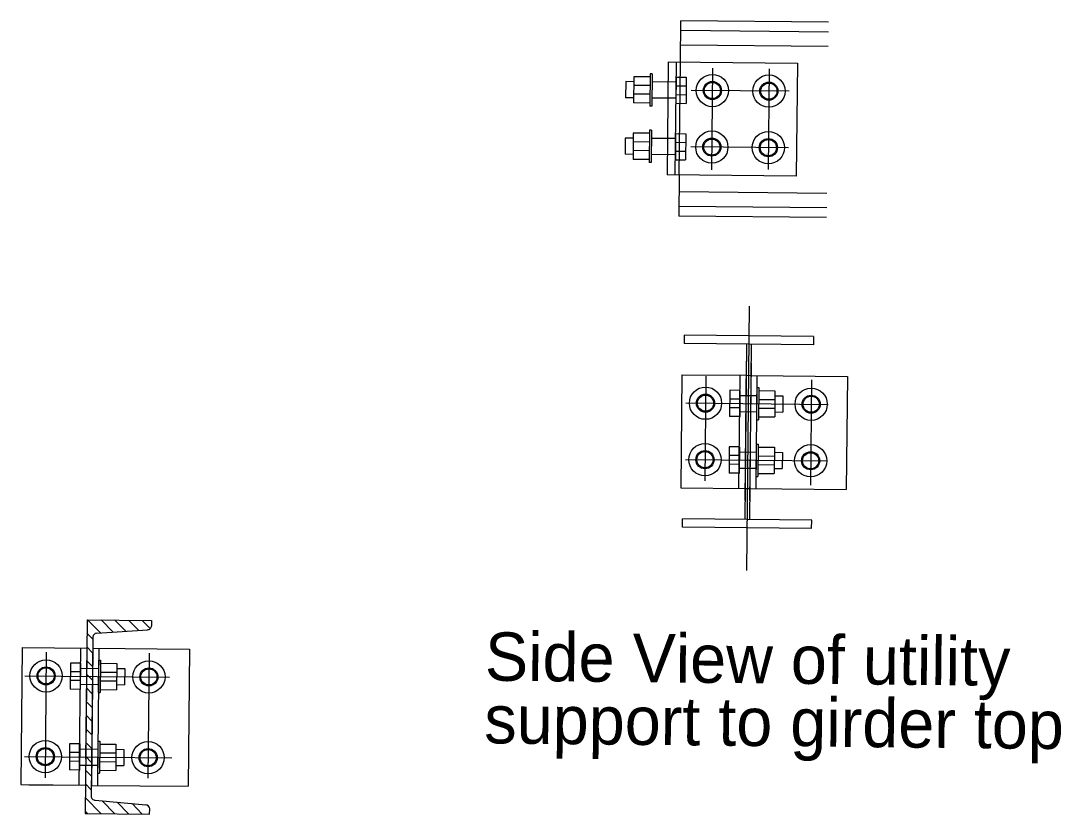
# Model space of a CAD drawing. Extents: x 632312 to 632885, y 378199 to 378534.
# Drawn here: x 632384.32 to 632389.7, y 378392.46 to 378396.56 of the extents above; entities that cross this region are included whole.
import ezdxf

# ---------------------------------------------------------------- set-up
doc = ezdxf.new("R2010")
doc.units = 0
for name, color, linetype in [('B_Boring', 7, 'Continuous'), ('R_Proposed Const Limits Cut', 7, 'Continuous'), ('R_Wall', 7, 'Continuous'), ('SHT_Dimensions', 7, 'Continuous'), ('USACE_Easement', 7, 'Continuous')]:
    doc.layers.add(name, color=color, linetype=linetype)

msp = doc.modelspace()

# ---------------------------------------------------------------- linework, layer by layer
at = {"layer": 'B_Boring'}
for p, q in [((632387.7302, 378396.3471), (632387.7323, 378396.5596)), ((632388.4951, 378396.552), (632387.7323, 378396.5596)), ((632388.4946, 378396.5016), (632387.7318, 378396.5091)), ((632387.6677, 378396.3477), (632387.6619, 378395.7644)), ((632387.6677, 378396.3477), (632388.3344, 378396.3411)), ((632387.7036, 378395.764), (632387.7094, 378396.3473)), ((632388.3344, 378396.3411), (632388.3286, 378395.7578)), ((632387.4899, 378396.2713), (632387.4885, 378396.1359)), ((632387.5732, 378396.2705), (632387.4899, 378396.2713)), ((632387.5734, 378396.2861), (632387.5717, 378396.1195)), ((632387.5838, 378396.286), (632387.5734, 378396.2861)), ((632387.5838, 378396.286), (632387.5821, 378396.1194)), ((632387.7086, 378396.2692), (632387.7073, 378396.1338)), ((632387.7086, 378396.2692), (632387.7607, 378396.2686)), ((632387.7607, 378396.2686), (632387.7593, 378396.1332)), ((632387.4479, 378396.2457), (632387.4471, 378396.1624)), ((632387.4896, 378396.2453), (632387.4479, 378396.2457)), ((632387.5728, 378396.2254), (632387.4894, 378396.2262)), ((632387.7084, 378396.2431), (632387.5834, 378396.2444)), ((632387.7082, 378396.224), (632387.7602, 378396.2235)), ((632387.4888, 378396.162), (632387.4471, 378396.1624)), ((632387.5723, 378396.1802), (632387.489, 378396.1811)), ((632387.7075, 378396.1598), (632387.5825, 378396.161)), ((632387.7077, 378396.1789), (632387.7598, 378396.1784)), ((632387.5719, 378396.1351), (632387.4885, 378396.1359)), ((632387.5821, 378396.1194), (632387.5717, 378396.1195)), ((632387.7073, 378396.1338), (632387.7593, 378396.1332)), ((632387.5705, 378395.9945), (632387.5688, 378395.8278)), ((632387.5809, 378395.9944), (632387.5705, 378395.9945)), ((632387.5809, 378395.9944), (632387.5792, 378395.8277)), ((632387.445, 378395.9541), (632387.4442, 378395.8707)), ((632387.4867, 378395.9536), (632387.445, 378395.9541)), ((632387.487, 378395.9797), (632387.4856, 378395.8443)), ((632387.5699, 378395.9337), (632387.4865, 378395.9346)), ((632387.5703, 378395.9789), (632387.487, 378395.9797)), ((632387.7055, 378395.9515), (632387.5805, 378395.9527)), ((632387.7057, 378395.9775), (632387.7044, 378395.8421)), ((632387.7053, 378395.9324), (632387.7573, 378395.9319)), ((632387.7057, 378395.9775), (632387.7578, 378395.977)), ((632387.7578, 378395.977), (632387.7564, 378395.8416)), ((632387.5694, 378395.8886), (632387.4861, 378395.8894)), ((632387.7048, 378395.8872), (632387.7569, 378395.8867)), ((632387.4859, 378395.8703), (632387.4442, 378395.8707)), ((632387.569, 378395.8435), (632387.4856, 378395.8443)), ((632387.5792, 378395.8277), (632387.5688, 378395.8278)), ((632387.7046, 378395.8681), (632387.5796, 378395.8694)), ((632387.7044, 378395.8421), (632387.7564, 378395.8416)), ((632388.3286, 378395.7578), (632387.6619, 378395.7644)), ((632387.7244, 378395.7638), (632387.7223, 378395.5513)), ((632388.4851, 378395.5437), (632387.7223, 378395.5513)), ((632388.4856, 378395.5941), (632387.7228, 378395.6017)), ((632387.7503, 378394.9372), (632387.7498, 378394.8943)), ((632388.4177, 378394.9306), (632387.7503, 378394.9372)), ((632388.4177, 378394.9306), (632388.4173, 378394.8877)), ((632388.4173, 378394.8877), (632387.7498, 378394.8943)), ((632388.0713, 378394.8911), (632388.0623, 378393.9853)), ((632388.0959, 378394.8909), (632388.0869, 378393.9851)), ((632387.7382, 378394.7332), (632387.7324, 378394.1499)), ((632387.7382, 378394.7332), (632388.0697, 378394.7299)), ((632388.0326, 378394.1469), (632388.0384, 378394.7302)), ((632388.0943, 378394.7297), (632388.5923, 378394.7247)), ((632388.1255, 378394.7293), (632388.1197, 378394.146)), ((632388.5923, 378394.7247), (632388.5865, 378394.1414)), ((632387.9855, 378394.6526), (632387.9842, 378394.5172)), ((632388.0376, 378394.6521), (632387.9855, 378394.6526)), ((632388.0376, 378394.6521), (632388.0363, 378394.5167)), ((632388.1249, 378394.6668), (632388.1232, 378394.5002)), ((632388.1249, 378394.6668), (632388.1353, 378394.6667)), ((632388.1353, 378394.6667), (632388.1336, 378394.5001)), ((632388.1351, 378394.6511), (632388.2185, 378394.6503)), ((632388.2185, 378394.6503), (632388.2171, 378394.5149)), ((632388.0372, 378394.607), (632387.9851, 378394.6075)), ((632388.1347, 378394.606), (632388.218, 378394.6052)), ((632388.2182, 378394.6242), (632388.2599, 378394.6238)), ((632388.2599, 378394.6238), (632388.259, 378394.5405)), ((632388.0367, 378394.5618), (632387.9847, 378394.5623)), ((632388.1342, 378394.5608), (632388.2176, 378394.56)), ((632388.2174, 378394.5409), (632388.259, 378394.5405)), ((632388.0363, 378394.5167), (632387.9842, 378394.5172)), ((632388.1232, 378394.5002), (632388.1336, 378394.5001)), ((632388.1338, 378394.5157), (632388.2171, 378394.5149)), ((632388.122, 378394.3752), (632388.1203, 378394.2085)), ((632388.122, 378394.3752), (632388.1324, 378394.3751)), ((632388.1324, 378394.3751), (632388.1307, 378394.2084)), ((632387.9826, 378394.3609), (632387.9813, 378394.2255)), ((632388.0343, 378394.3153), (632387.9822, 378394.3158)), ((632388.0347, 378394.3604), (632387.9826, 378394.3609)), ((632388.0347, 378394.3604), (632388.0334, 378394.225)), ((632388.1322, 378394.3594), (632388.2156, 378394.3586)), ((632388.2156, 378394.3586), (632388.2142, 378394.2232)), ((632388.2153, 378394.3326), (632388.257, 378394.3321)), ((632388.257, 378394.3321), (632388.2561, 378394.2488)), ((632388.0338, 378394.2701), (632387.9818, 378394.2706)), ((632388.1313, 378394.2692), (632388.2147, 378394.2683)), ((632388.1318, 378394.3143), (632388.2151, 378394.3135)), ((632388.0334, 378394.225), (632387.9813, 378394.2255)), ((632388.1203, 378394.2085), (632388.1307, 378394.2084)), ((632388.1309, 378394.224), (632388.2142, 378394.2232)), ((632388.2145, 378394.2492), (632388.2561, 378394.2488)), ((632387.7324, 378394.1499), (632388.0639, 378394.1466)), ((632388.0885, 378394.1463), (632388.5865, 378394.1414)), ((632387.7404, 378393.9456), (632387.7408, 378393.9885)), ((632388.4079, 378393.939), (632387.7404, 378393.9456)), ((632388.4083, 378393.9819), (632387.7408, 378393.9885)), ((632388.4079, 378393.939), (632388.4083, 378393.9819)), ((632384.6666, 378393.4682), (632384.6566, 378392.4683)), ((632384.6666, 378393.4682), (632384.9998, 378393.4649)), ((632384.7356, 378393.4002), (632384.669, 378393.4682)), ((632384.8012, 378393.4048), (632384.7397, 378393.4675)), ((632384.8667, 378393.4094), (632384.8104, 378393.4668)), ((632384.9322, 378393.414), (632384.8811, 378393.4661)), ((632384.9933, 378393.4231), (632384.9518, 378393.4654)), ((632384.9998, 378393.4649), (632384.9996, 378393.4378)), ((632384.7175, 378393.399), (632384.9786, 378393.4172)), ((632384.6964, 378393.3688), (632384.6659, 378393.4)), ((632384.6965, 378393.3783), (632384.6883, 378392.5575)), ((632384.3318, 378393.3257), (632384.3247, 378392.6174)), ((632384.3318, 378393.3257), (632384.6651, 378393.3224)), ((632384.6268, 378392.6144), (632384.6339, 378393.3227)), ((632384.6957, 378393.2981), (632384.6652, 378393.3293)), ((632384.6959, 378393.3221), (632385.1959, 378393.3171)), ((632384.7272, 378393.3218), (632384.7201, 378392.6135)), ((632385.1959, 378393.3171), (632385.1889, 378392.6088)), ((632384.581, 378393.2451), (632384.5796, 378393.1097)), ((632384.6331, 378393.2446), (632384.581, 378393.2451)), ((632384.6331, 378393.2446), (632384.6317, 378393.1092)), ((632384.695, 378393.2274), (632384.6645, 378393.2586)), ((632384.7266, 378393.2593), (632384.7249, 378393.0926)), ((632384.7266, 378393.2593), (632384.737, 378393.2592)), ((632384.737, 378393.2592), (632384.7353, 378393.0925)), ((632384.7368, 378393.2435), (632384.8202, 378393.2427)), ((632384.8202, 378393.2427), (632384.8188, 378393.1073)), ((632384.6326, 378393.1994), (632384.5805, 378393.2)), ((632384.6943, 378393.1567), (632384.6638, 378393.1878)), ((632384.7364, 378393.1984), (632384.8197, 378393.1976)), ((632384.8199, 378393.2167), (632384.8616, 378393.2163)), ((632384.8616, 378393.2163), (632384.8607, 378393.1329)), ((632384.6322, 378393.1543), (632384.5801, 378393.1548)), ((632384.7359, 378393.1533), (632384.8193, 378393.1524)), ((632384.8191, 378393.1334), (632384.8607, 378393.1329)), ((632384.6317, 378393.1092), (632384.5796, 378393.1097)), ((632384.6936, 378393.086), (632384.6631, 378393.1171)), ((632384.7249, 378393.0926), (632384.7353, 378393.0925)), ((632384.7355, 378393.1081), (632384.8188, 378393.1073)), ((632384.6929, 378393.0153), (632384.6624, 378393.0464)), ((632384.6922, 378392.9446), (632384.6617, 378392.9757)), ((632384.6915, 378392.8739), (632384.661, 378392.905)), ((632384.5769, 378392.8284), (632384.5755, 378392.693)), ((632384.6289, 378392.8279), (632384.5769, 378392.8284)), ((632384.6289, 378392.8279), (632384.6276, 378392.6925)), ((632384.6908, 378392.8032), (632384.6602, 378392.8343)), ((632384.7224, 378392.8426), (632384.7208, 378392.676)), ((632384.7224, 378392.8426), (632384.7328, 378392.8425)), ((632384.7328, 378392.8425), (632384.7312, 378392.6759)), ((632384.7327, 378392.8269), (632384.816, 378392.8261)), ((632384.816, 378392.8261), (632384.8147, 378392.6907)), ((632384.6285, 378392.7828), (632384.5764, 378392.7833)), ((632384.6901, 378392.7325), (632384.6595, 378392.7636)), ((632384.7322, 378392.7818), (632384.8156, 378392.7809)), ((632384.8157, 378392.8), (632384.8574, 378392.7996)), ((632384.8574, 378392.7996), (632384.8566, 378392.7163)), ((632384.628, 378392.7377), (632384.576, 378392.7382)), ((632384.7318, 378392.7366), (632384.8151, 378392.7358)), ((632384.8149, 378392.7167), (632384.8566, 378392.7163)), ((632384.6276, 378392.6925), (632384.5755, 378392.693)), ((632384.6894, 378392.6618), (632384.6588, 378392.6929)), ((632384.7208, 378392.676), (632384.7312, 378392.6759)), ((632384.7313, 378392.6915), (632384.8147, 378392.6907)), ((632384.3247, 378392.6174), (632384.6581, 378392.6141)), ((632384.6887, 378392.5911), (632384.6581, 378392.6222)), ((632384.6889, 378392.6138), (632385.1889, 378392.6088)), ((632384.7398, 378392.4674), (632384.6574, 378392.5515)), ((632384.7089, 378392.5365), (632384.9696, 378392.5131)), ((632384.8105, 378392.4667), (632384.7454, 378392.5332)), ((632384.8812, 378392.466), (632384.8221, 378392.5263)), ((632384.9519, 378392.4653), (632384.8989, 378392.5194)), ((632384.9891, 378392.4988), (632384.9763, 378392.5119)), ((632384.9899, 378392.465), (632384.9902, 378392.4921)), ((632384.6597, 378392.4682), (632384.6566, 378392.4714)), ((632384.6566, 378392.4683), (632384.9899, 378392.465)), ((632384.6566, 378392.4683), (632384.9899, 378392.465)), ((632384.6691, 378392.4681), (632384.6567, 378392.4808))]:
    msp.add_line(p, q, dxfattribs=at)
for centre in [(632387.8954, 378396.1996), (632388.1871, 378396.1967), (632387.8925, 378395.9079), (632388.1842, 378395.905), (632387.8599, 378394.5861), (632388.4053, 378394.5807), (632387.857, 378394.2945), (632388.4024, 378394.289), (632384.4553, 378393.1786), (632384.9861, 378393.1734), (632384.4512, 378392.762), (632384.982, 378392.7567)]:
    msp.add_circle(centre, 0.0469, dxfattribs=at)
for centre, start, end in [((632384.9788, 378393.438), 269.4304, 359.4388), ((632384.7173, 378393.3781), 89.4304, 179.4304), ((632384.7091, 378392.5573), 179.4304, 269.4304), ((632384.9694, 378392.4923), 359.4304, 89.4304)]:
    msp.add_arc(centre, 0.0208, start, end, dxfattribs=at)
at = {"layer": 'R_Proposed Const Limits Cut'}
for p, q in [((632388.4939, 378396.427), (632387.7311, 378396.4346)), ((632387.7244, 378395.7638), (632387.7302, 378396.3471)), ((632388.4863, 378395.6687), (632387.7236, 378395.6763)), ((632388.0697, 378394.7299), (632388.0943, 378394.7297)), ((632388.0374, 378394.626), (632388.1245, 378394.6252)), ((632388.0365, 378394.5427), (632388.1236, 378394.5419)), ((632388.0345, 378394.3344), (632388.1216, 378394.3335)), ((632388.0336, 378394.251), (632388.1207, 378394.2502)), ((632388.0639, 378394.1466), (632388.0885, 378394.1463)), ((632384.6328, 378393.2185), (632384.7261, 378393.2176)), ((632384.632, 378393.1352), (632384.7253, 378393.1343)), ((632384.6287, 378392.8019), (632384.722, 378392.801)), ((632384.6278, 378392.7186), (632384.7212, 378392.7176))]:
    msp.add_line(p, q, dxfattribs=at)
for centre, radius in [((632387.8954, 378396.1996), 0.0833), ((632388.1871, 378396.1967), 0.0833), ((632387.8954, 378396.1996), 0.0417), ((632388.1871, 378396.1967), 0.0417), ((632387.8925, 378395.9079), 0.0833), ((632388.1842, 378395.905), 0.0833), ((632387.8925, 378395.9079), 0.0417), ((632388.1842, 378395.905), 0.0417), ((632387.8599, 378394.5861), 0.0833), ((632388.4053, 378394.5807), 0.0833), ((632387.8599, 378394.5861), 0.0417), ((632388.4053, 378394.5807), 0.0417), ((632387.857, 378394.2945), 0.0833), ((632388.4024, 378394.289), 0.0833), ((632387.857, 378394.2945), 0.0417), ((632388.4024, 378394.289), 0.0417), ((632384.4553, 378393.1786), 0.0833), ((632384.9861, 378393.1734), 0.0833), ((632384.4553, 378393.1786), 0.0417), ((632384.9861, 378393.1734), 0.0417), ((632384.4512, 378392.762), 0.0833), ((632384.982, 378392.7567), 0.0833), ((632384.4512, 378392.762), 0.0417), ((632384.982, 378392.7567), 0.0417)]:
    msp.add_circle(centre, radius, dxfattribs=at)
at = {"layer": 'R_Wall'}
for p, q in [((632387.8966, 378396.3152), (632387.8914, 378395.7907)), ((632388.1882, 378396.3123), (632388.1831, 378395.7922)), ((632388.2912, 378396.1957), (632387.7865, 378396.2007)), ((632388.2883, 378395.904), (632387.7836, 378395.909)), ((632388.0855, 378395.0869), (632388.0719, 378393.7227)), ((632387.8613, 378394.7253), (632387.8559, 378394.1857)), ((632388.4065, 378394.707), (632388.4011, 378394.1622)), ((632387.759, 378394.5871), (632388.4929, 378394.5798)), ((632387.7561, 378394.2955), (632388.49, 378394.2882)), ((632384.4565, 378393.3014), (632384.4501, 378392.6533)), ((632384.9874, 378393.2961), (632384.9809, 378392.651)), ((632384.3462, 378393.1797), (632385.0931, 378393.1723)), ((632384.3446, 378392.763), (632385.105, 378392.7555))]:
    msp.add_line(p, q, dxfattribs=at)
at = {"layer": 'SHT_Dimensions'}
for p, q in [((632388.0704, 378394.8028), (632388.0632, 378394.0841)), ((632388.0949, 378394.7921), (632388.0878, 378394.0838)), ((632384.6652, 378393.3328), (632384.6594, 378392.7495)), ((632384.6959, 378393.3221), (632384.6889, 378392.6138)), ((632384.3664, 378392.617), (632384.6581, 378392.6141))]:
    msp.add_line(p, q, dxfattribs=at)
for radius in [0.0833, 0.0469]:
    msp.add_circle((632387.8954, 378396.1996), radius, dxfattribs=at)

# ---------------------------------------------------------------- texts
at = {"layer": 'USACE_Easement'}
for s, p in [('Side View of utility ', (632386.7202, 378393.1543)), ('support to girder top', (632386.717, 378392.8308))]:
    msp.add_text(s, height=0.25, rotation=359.4304, dxfattribs=at).set_placement(p)

doc.saveas('drawing.dxf')
